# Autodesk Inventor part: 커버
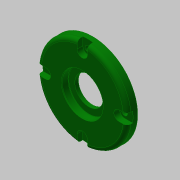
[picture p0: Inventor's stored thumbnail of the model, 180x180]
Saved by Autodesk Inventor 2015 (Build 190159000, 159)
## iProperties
Created: 2020-05
Part Number: 커버
Material: 알루미늄 6061
Document SubType Name: Modeling
Designer: mduedu
Density: 1 g/cm^3
Appearance: 진녹색
Author: mduedu
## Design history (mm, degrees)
sketch "스케치1"
  geometry: L1 (0, 0)-(8, 0); L2 (8, 0)-(8, 35); L3 (8, 35)-(0, 35); L4 (0, 35)-(0, 0); L5 (8, 0)-(12, 0); L6 (12, 0)-(12, 23.5); L7 (12, 23.5)-(8, 23.5); L8 (8, 23.5)-(8, 0)
  constraints: 16 end point, 4 parallel, 2 horizontal, 2 perpendicular
  dimensions: "d0" = 70 diameter of L3 L1; "d2" = 47 diameter of L7 L5; "d3" = 4 distance of L6.end L7.end; "d4" = 12 distance between parallel lines of L4 L6
revolve "회전1" sketch "스케치1" stored, may be unused: angle "d5" = 90 deg
hole "구멍1" diameter "d8" = 22; stored, may be unused: countersink angle "d12" = 90 deg, drill point angle "d14" = 118 deg; dims "d6" = 10, "d7" = 10, "d9" = 6, "d10" = 32, "d11" = 5.2, "d13" = 8
hole "구멍2" diameter "d17" = 40; stored, may be unused: countersink angle "d21" = 90 deg, drill point angle "d23" = 0 deg; dims "d15" = 10, "d16" = 10, "d18" = 6, "d19" = 32, "d20" = 5.2, "d22" = 4
fillet "모깎기1" dims "d24" = 3
fillet "모깎기2" dims "d25" = 3
fillet "모깎기3" dims "d26" = 0.3
chamfer "모따기1" distance "d27" = 0.5; stored, may be unused: second distance "d28" = 2, angle "d29" = 30 deg
chamfer "모따기2" distance "d30" = 1; stored, may be unused: second distance "d31" = 2, angle "d32" = 30 deg
sketch "스케치2" dims "d33" = 57
  geometry: L1 (-4, 28.5)-(4, 28.5); L2 (4, 28.5)-(4, 38.5); L3 (4, 38.5)-(-4, 38.5); L4 (-4, 38.5)-(-4, 28.5); 4 further points
  constraints: 8 end point, 2 horizontal alignment, 2 midpoint, 2 parallel, 2 vertical alignment, 1 coincident, 1 horizontal, 1 perpendicular, 6 other
  dimensions: "d34" = 8 distance between parallel lines of L2 L4; "d35" = 10 distance of point (0, 28.5) point (0, 38.5)
extrude "돌출1" cut sketch "스케치2" distance "d36" = 4.4; taper "d37" = 0 deg
sketch "스케치3"
  geometry: A1 r 4 centre (0, 28.5) between (-4, 28.5) and (4, 28.5) reference; 2 further points
  constraints: 1 coincident
hole "구멍3" sketch "스케치3" at (0, 28.5) diameter "d38" = 4.5; stored, may be unused: countersink angle "d42" = 90 deg, drill point angle "d44" = 0 deg; dims "d39" = 6, "d40" = 32, "d41" = 5.2, "d43" = 4
node "솔리드1"
pattern_circular "원형 패턴1" dims angle "d46" = 360 deg
